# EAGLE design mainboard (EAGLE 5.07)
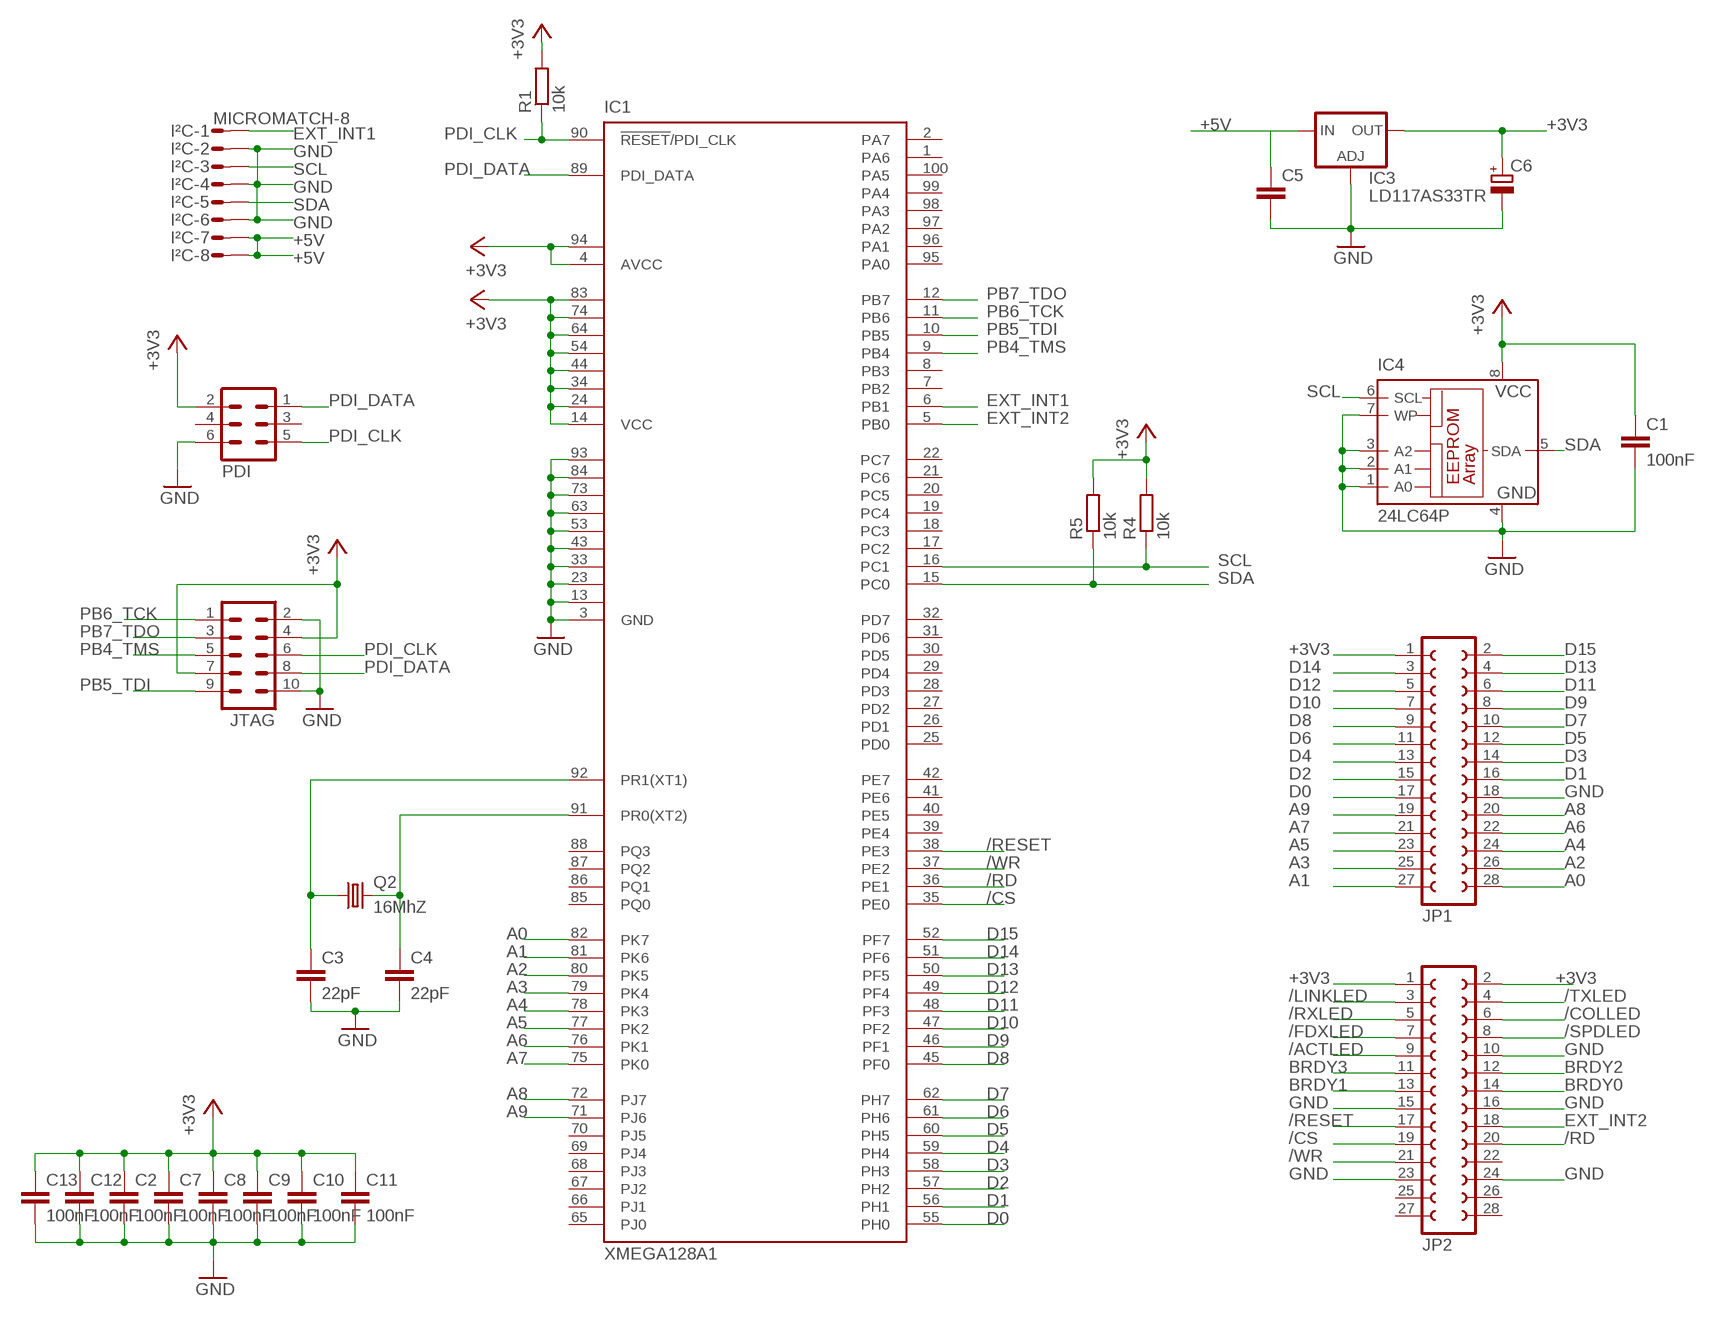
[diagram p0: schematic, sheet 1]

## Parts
C1  100nF  C-EUC0805  [C0805]
C2  100nF  C-EUC0805  [C0805]
C3  22pF  C-EUC0805  [C0805]
C4  22pF  C-EUC0805  [C0805]
C5  C-EUC0805  [C0805]
C6  CPOL-EU085CS-1AR  [085CS_1AR]
C7  100nF  C-EUC0805  [C0805]
C8  100nF  C-EUC0805  [C0805]
C9  100nF  C-EUC0805  [C0805]
C10  100nF  C-EUC0805  [C0805]
C11  100nF  C-EUC0805  [C0805]
C12  100nF  C-EUC0805  [C0805]
C13  100nF  C-EUC0805  [C0805]
IC1  XMEGA128A1  [TQFP100]
IC3  LD117AS33TR  [SOT223]
IC4  24LC64P  [DIL8]
I²C  MICROMATCH-8  [MICROMATCH-8]
JP1  FE15-2  [FE15-2]
JP2  FE15-2  [FE15-2]
JTAG  MA05-2  [MA05-2]
PDI  MA03-2  [MA03-2]
Q2  16MhZ  CRYSTALSM49  [SM49]
R1  10k  R-EU_M0805  [M0805]
R4  10k  R-EU_M0805  [M0805]
R5  10k  R-EU_M0805  [M0805]

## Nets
+3V3: C1.1 C2.1 C6.+ C7.1 C8.1 C9.1 C10.1 C11.1 C12.1 C13.1 IC1.4(AVCC) IC1.14(VCC) IC1.24(VCC1) IC1.34(VCC2) IC1.44(VCC3) IC1.54(VCC4) IC1.64(VCC5) IC1.74(VCC6) IC1.83(VCC7) IC1.94(AVCC1) IC3.4(OUT) IC4.8(VCC) JP1.1 JP2.1 JP2.2 JTAG.4 JTAG.7 PDI.2 R1.2 R4.2 R5.2
+5V: C5.1 IC3.3(IN) I²C.7 I²C.8
/ACTLED: JP2.9
/COLLED: JP2.6
/CS: IC1.35(PE0) JP2.19
/FDXLED: JP2.7
/LINKLED: JP2.3
/RD: IC1.36(PE1) JP2.20
/RESET: IC1.38(PE3) JP2.17
/RXLED: JP2.5
/SPDLED: JP2.8
/TXLED: JP2.4
/WR: IC1.37(PE2) JP2.21
A0: IC1.82(PK7) JP1.28
A1: IC1.81(PK6) JP1.27
A2: IC1.80(PK5) JP1.26
A3: IC1.79(PK4) JP1.25
A4: IC1.78(PK3) JP1.24
A5: IC1.77(PK2) JP1.23
A6: IC1.76(PK1) JP1.22
A7: IC1.75(PK0) JP1.21
A8: IC1.72(PJ7) JP1.20
A9: IC1.71(PJ6) JP1.19
BRDY0: JP2.14
BRDY1: JP2.13
BRDY2: JP2.12
BRDY3: JP2.11
D0: IC1.55(PH0) JP1.17
D1: IC1.56(PH1) JP1.16
D2: IC1.57(PH2) JP1.15
D3: IC1.58(PH3) JP1.14
D4: IC1.59(PH4) JP1.13
D5: IC1.60(PH5) JP1.12
D6: IC1.61(PH6) JP1.11
D7: IC1.62(PH7) JP1.10
D8: IC1.45(PF0) JP1.9
D9: IC1.46(PF1) JP1.8
D10: IC1.47(PF2) JP1.7
D11: IC1.48(PF3) JP1.6
D12: IC1.49(PF4) JP1.5
D13: IC1.50(PF5) JP1.4
D14: IC1.51(PF6) JP1.3
D15: IC1.52(PF7) JP1.2
EXT_INT1: IC1.6(PB1) I²C.1
EXT_INT2: IC1.5(PB0) JP2.18
GND: C1.2 C2.2 C3.2 C4.2 C5.2 C6.- C7.2 C8.2 C9.2 C10.2 C11.2 C12.2 C13.2 IC1.3(GND) IC1.13(GND1) IC1.23(GND2) IC1.33(GND3) IC1.43(GND4) IC1.53(GND5) IC1.63(GND6) IC1.73(GND7) IC1.84(GND8) IC1.93(GND9) IC3.1(ADJ) IC4.1(A0) IC4.2(A1) IC4.3(A2) IC4.4(GND) IC4.7(WP) I²C.2 I²C.4 I²C.6 JP1.18 JP2.10 JP2.15 JP2.16 JP2.23 JP2.24 JTAG.2 JTAG.10 PDI.6
N$5: C3.1 IC1.92(PR1(XT1)) Q2.1
N$6: C4.1 IC1.91(PR0(XT2)) Q2.2
PB4_TMS: IC1.9(PB4) JTAG.5
PB5_TDI: IC1.10(PB5) JTAG.9
PB6_TCK: IC1.11(PB6) JTAG.1
PB7_TDO: IC1.12(PB7) JTAG.3
PDI_CLK: IC1.90(!RESET!/PDI_CLK) JTAG.6 PDI.5 R1.1
PDI_DATA: IC1.89(PDI_DATA) JTAG.8 PDI.1
SCL: IC1.16(PC1) IC4.6(SCL) I²C.3 R4.1
SDA: IC1.15(PC0) IC4.5(SDA) I²C.5 R5.1
Unconnected: IC1.1(PA6) IC1.2(PA7) IC1.7(PB2) IC1.8(PB3) IC1.17(PC2) IC1.18(PC3) IC1.19(PC4) IC1.20(PC5) IC1.21(PC6) IC1.22(PC7) IC1.25(PD0) IC1.26(PD1) IC1.27(PD2) IC1.28(PD3) IC1.29(PD4) IC1.30(PD5) IC1.31(PD6) IC1.32(PD7) IC1.39(PE4) IC1.40(PE5) IC1.41(PE6) IC1.42(PE7) IC1.65(PJ0) IC1.66(PJ1) IC1.67(PJ2) IC1.68(PJ3) IC1.69(PJ4) IC1.70(PJ5) IC1.85(PQ0) IC1.86(PQ1) IC1.87(PQ2) IC1.88(PQ3) IC1.95(PA0) IC1.96(PA1) IC1.97(PA2) IC1.98(PA3) IC1.99(PA4) IC1.100(PA5) JP2.22 JP2.25 JP2.26 JP2.27 JP2.28 PDI.3 PDI.4

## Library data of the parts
C1-C5 C7-C13 = rcl:C-EU: CAPACITOR, European symbol
C6 = rcl:CPOL-EU: POLARIZED CAPACITOR, European symbol
IC1 = atmel:XMEGA128A1: MICROCONTROLLER Features High-performance, Low-power 8/16-bit AVR XMEGA Microcontroller Non-Volatile Program and Data Memories - 64K - 384K Bytes of In-System Self-Programmable Flash - 4K - 8K Bytes Boot Section with Independent Lock Bits - 2 KB - 4 KB EEPROM - 4 KB - 32 KB Internal SRAM External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
IC3 = v-reg:LD117A?*: Low drop fixed and adjustable positive voltage regulators 1 A Source: http://www.st.com/stonline/products/literature/ds/7194/ld1117axx.pdf
IC4 = microchip:24*: Serial EEPROM I2C
I²C = con-amp-micromatch:MICROMATCH-8: MicroMaTch 8 7-215464-8 / 0-215464-8 Drawing Number C-215464 DDEController.pdf
JP1 JP2 = con-FE-neu:FE15-2: FEMALE HEADER
JTAG = con-lstb:MA05-2: PIN HEADER
PDI = con-lstb:MA03-2: PIN HEADER
Q2 = crystal:CRYSTAL: CRYSTAL
R1 R4 R5 = rcl:R-EU_: RESISTOR, European symbol

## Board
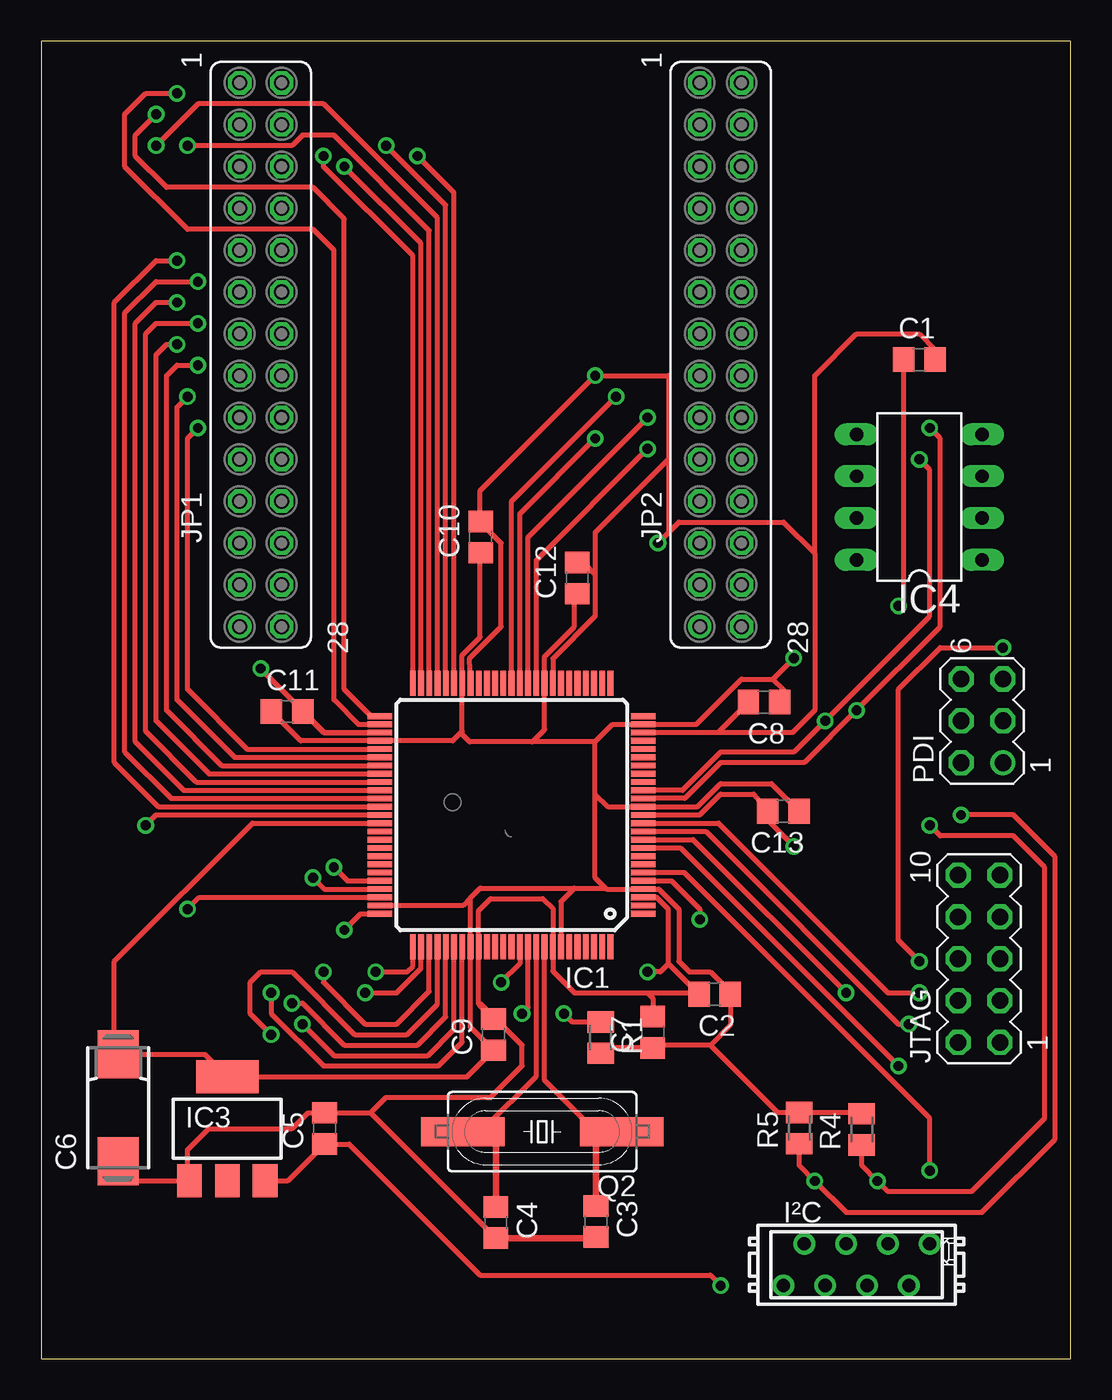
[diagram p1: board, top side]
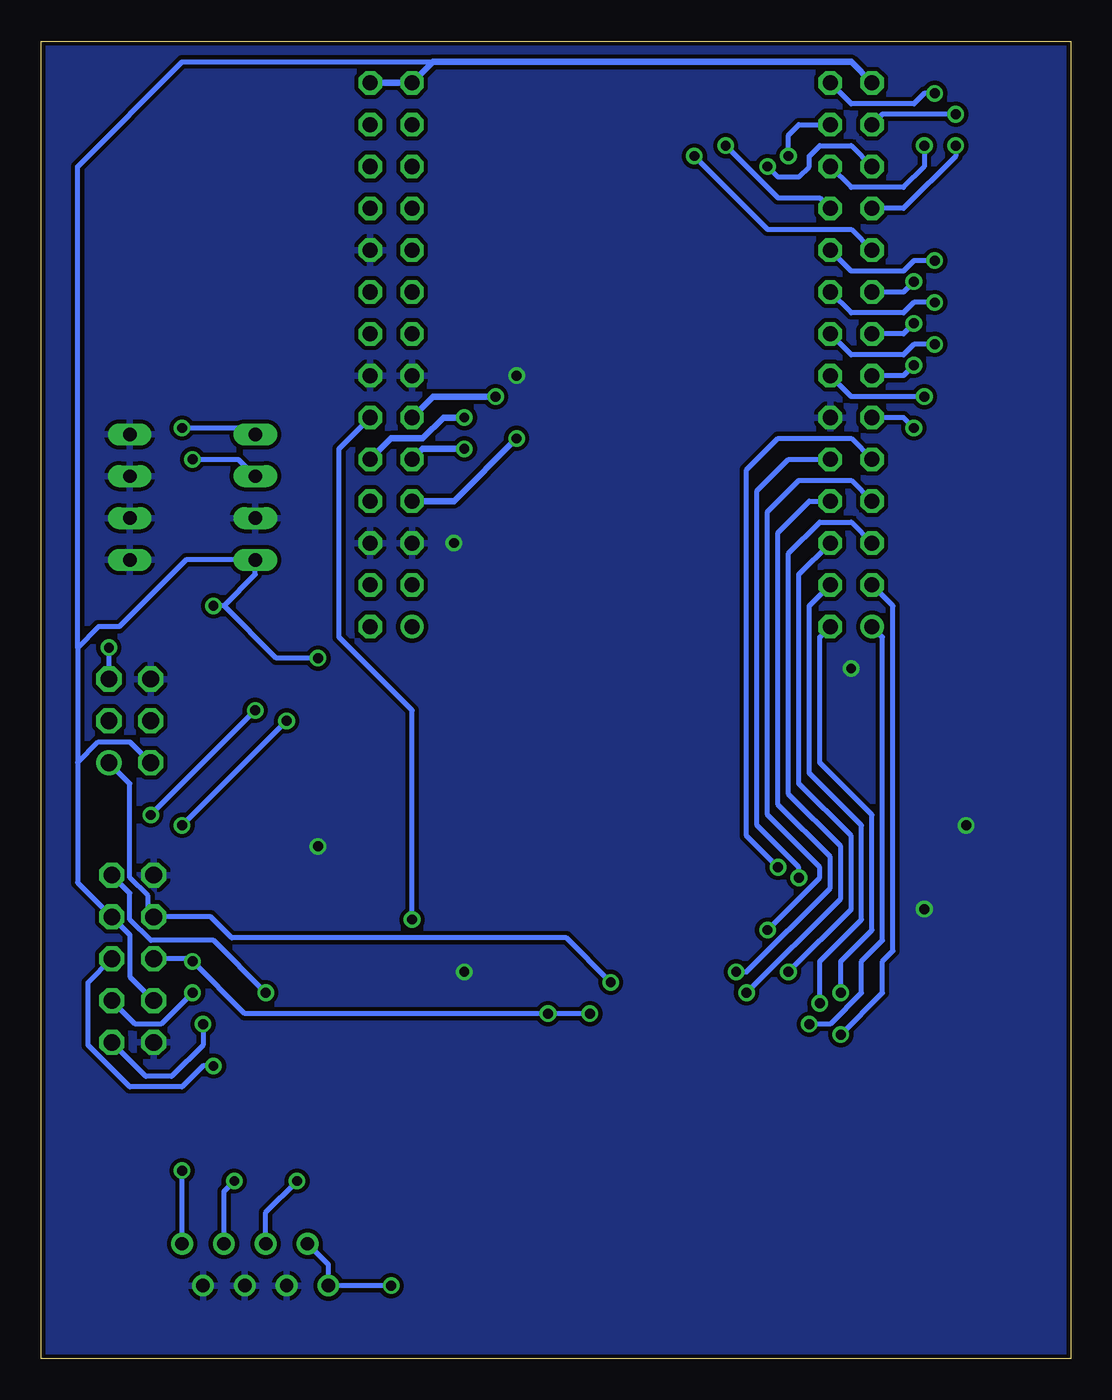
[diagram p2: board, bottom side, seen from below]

Size 62.54 x 80 mm. Coordinates in mm from the lower left corner, seen from the top.
Outline: 0,0 62.54,0 62.54,80 0,80 0,0
Copper layers (1*16): Top 0.035mm / dielectric 1.5mm / Bottom 0.035mm
Design rules "EMST": minimum track width 10mil, minimum drill 0.6mm, track to track 10mil, track to pad 10mil, pad to pad 10mil, via to via 10mil, smd to smd 8mil, copper to edge 10mil, drill to drill 10mil, minimum pad ring 10mil, minimum via ring 8mil, stop-mask expansion 4mil, vias tented up to drill 0mil, thermal gap 10mil

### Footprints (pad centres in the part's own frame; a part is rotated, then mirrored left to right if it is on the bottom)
C0805 = smd 1.3 x 1.5: 1 -0.95,0; 2 0.95,0
085CS_1AR = smd 2.9 x 2.5: + 3.25,0; - -3.25,0
TQFP100 = smd 1.5 x 0.35: 1 -8,6; 2 -8,5.5; 3 -8,5; 4 -8,4.5; 5 -8,4; 6 -8,3.5; 7 -8,3; 8 -8,2.5; 9 -8,2; 10 -8,1.5; 11 -8,1; 12 -8,0.5; 13 -8,0; 14 -8,-0.5; 15 -8,-1; 16 -8,-1.5; 17 -8,-2; 18 -8,-2.5; 19 -8,-3; 20 -8,-3.5; 21 -8,-4; 22 -8,-4.5; 23 -8,-5; 24 -8,-5.5; 25 -8,-6; 51 8,-6; 52 8,-5.5; 53 8,-5; 54 8,-4.5; 55 8,-4; 56 8,-3.5; 57 8,-3; 58 8,-2.5; 59 8,-2; 60 8,-1.5; 61 8,-1; 62 8,-0.5; 63 8,0; 64 8,0.5; 65 8,1; 66 8,1.5; 67 8,2; 68 8,2.5; 69 8,3; 70 8,3.5; 71 8,4; 72 8,4.5; 73 8,5; 74 8,5.5; 75 8,6 | smd 0.35 x 1.5: 26 -6,-8; 27 -5.5,-8; 28 -5,-8; 29 -4.5,-8; 30 -4,-8; 31 -3.5,-8; 32 -3,-8; 33 -2.5,-8; 34 -2,-8; 35 -1.5,-8; 36 -1,-8; 37 -0.5,-8; 38 0,-8; 39 0.5,-8; 40 1,-8; 41 1.5,-8; 42 2,-8; 43 2.5,-8; 44 3,-8; 45 3.5,-8; 46 4,-8; 47 4.5,-8; 48 5,-8; 49 5.5,-8; 50 6,-8; 76 6,8; 77 5.5,8; 78 5,8; 79 4.5,8; 80 4,8; 81 3.5,8; 82 3,8; 83 2.5,8; 84 2,8; 85 1.5,8; 86 1,8; 87 0.5,8; 88 0,8; 89 -0.5,8; 90 -1,8; 91 -1.5,8; 92 -2,8; 93 -2.5,8; 94 -3,8; 95 -3.5,8; 96 -4,8; 97 -4.5,8; 98 -5,8; 99 -5.5,8; 100 -6,8
SOT223 = smd 1.5 x 2: 1 -2.3,-3.15; 2 0,-3.15; 3 2.3,-3.15 | smd 3.8 x 2: 4 0,3.15
DIL8 = drill 0.813 long: 1 -3.81,-3.81; 2 -1.27,-3.81; 3 1.27,-3.81; 4 3.81,-3.81; 5 3.81,3.81; 6 1.27,3.81; 7 -1.27,3.81; 8 -3.81,3.81
MICROMATCH-8 = drill 0.813 round: 1 4.445,1.27; 2 3.175,-1.27; 3 1.905,1.27; 4 0.635,-1.27; 5 -0.635,1.27; 6 -1.905,-1.27; 7 -3.175,1.27; 8 -4.445,-1.27
FE15-2 = drill 0.914 octagon: 1 15.24,1.27; 2 15.24,-1.27; 3 12.7,1.27; 4 12.7,-1.27; 5 10.16,1.27; 6 10.16,-1.27; 7 7.62,1.27; 8 7.62,-1.27; 9 5.08,1.27; 10 5.08,-1.27; 11 2.54,1.27; 12 2.54,-1.27; 13 0,1.27; 14 0,-1.27; 15 -2.54,1.27; 16 -2.54,-1.27; 17 -5.08,1.27; 18 -5.08,-1.27; 19 -7.62,1.27; 20 -7.62,-1.27; 21 -10.16,1.27; 22 -10.16,-1.27; 23 -12.7,1.27; 24 -12.7,-1.27; 25 -15.24,1.27; 26 -15.24,-1.27; 28 -17.78,-1.27 | drill 0.914 round: 27 -17.78,1.27
MA05-2 = drill 1.016 octagon: 1 -5.08,-1.27; 2 -5.08,1.27; 3 -2.54,-1.27; 4 -2.54,1.27; 5 0,-1.27; 6 0,1.27; 7 2.54,-1.27; 8 2.54,1.27; 9 5.08,-1.27; 10 5.08,1.27
MA03-2 = drill 1.016 round: 1 -2.54,-1.27 | drill 1.016 octagon: 2 -2.54,1.27; 3 0,-1.27; 4 0,1.27; 5 2.54,-1.27; 6 2.54,1.27
SM49 = smd 5.08 x 1.778: 1 -4.826,0; 2 4.826,0
M0805 = smd 1.3 x 1.6: 1 -0.95,0; 2 0.95,0

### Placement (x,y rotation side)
C1  53.34,60.66 0 top
C2  40.91,22.13 180 top
C3  33.7,8.34 270 top
C4  27.62,8.28 270 top
C5  17.22,13.99 90 top
C6  4.68,15.24 90 top
C7  37.16,19.83 90 top
C8  43.91,39.87 180 top
C9  27.48,19.68 90 top
C10  26.7,49.89 90 top
C11  14.94,39.3 0 top
C12  32.56,47.4 90 top
C13  45.09,33.25 180 top
IC1  28.58,33.02 180 top
IC3  11.3,13.97 0 top
IC4  53.34,52.31 90 top
I²C  49.53,5.71 0 top
JP1  13.33,62.23 90 top
JP2  41.27,62.23 90 top
JTAG  56.97,24.29 90 top
PDI  57.15,38.73 90 top
Q2  30.44,13.79 180 top
R1  33.98,19.5 270 top
R4  49.84,13.93 90 top
R5  46.05,14.01 90 top

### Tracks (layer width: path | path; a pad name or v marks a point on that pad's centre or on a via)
+3V3  (via drill 0.6)
  Top 0.305: C11.1 15.77,37.52 IC1.54 25,37.52 25.58,38.1 | C13.1 44.36,34.92 41.27,34.92 39.87,33.52 IC1.14 34.43,33.52 33.66,34.29 | C10.1 26.67,48.91 26.67,43.81 25.58,42.72 IC1.44 25.58,38.1 | C12.1 32.38,46.27 32.38,44.45 30.58,42.64 IC1.34 30.58,38.2 29.85,37.47 | 33.66,37.47 34.71,38.52 IC1.24 39.79,38.52 42.55,41.27 44.45,41.27 | C8.1 45.09,40.09 45.09,40.64 44.45,41.27 | 33.66,34.29 33.66,37.47 | 34.29,28.57 33.66,29.21 33.66,34.29 | 34.29,28.57 34.34,28.52 IC1.4 37.52,28.52 38.73,27.3 38.73,24.13 39.37,23.5 40.64,23.5 41.86,22.27 C2.1 41.86,20.27 40.64,19.05 | IC1.94 31.58,27.77 32.38,28.57 | 32.38,28.57 34.29,28.57 | 26.08,27.98 IC1.83 26.08,20.14 C9.1 25.87,17.12 IC3.4 9.93,18.49 C6.+ 4.45,18.73 4.45,24.13 12.83,32.52 IC1.64 | 26.08,27.98 26.67,28.57 32.38,28.57 | 33.66,37.47 29.85,37.47 | R4.2 49.76,14.96 R5.2 44.73,14.96 40.64,19.05 | 26.08,27.98 25.62,27.52 IC1.74 | v52.07,45.72 52.39,46.03 52.38,46.03 v52.07,45.72 | C1.1 52.39,46.04 v52.07,45.72 | 29.85,37.47 26.04,37.47 25.58,37.92 25.58,38.1 | 44.45,41.27 v45.72,42.55 | 40.64,19.05 37.33,19.05 C7.1 34.3,18.88 R1.2
  Top 0.406: C12.1 32.41,46.29
  Bottom 0.305: JTAG.4 57.15,23.2 57.15,25.74 JTAG.7 60.33,28.91 60.33,36.2 | 60.33,36.2 59.05,37.47 57.15,37.47 PDI.2 | 60.33,43.18 59.05,44.45 57.79,44.45 53.73,48.51 IC4.8 49.53,47.62 51.44,45.72 | 60.33,43.18 60.33,36.2 | 38.73,78.74 53.98,78.74 60.33,72.39 60.33,43.18 | 51.44,45.72 v52.07,45.72 | v45.72,42.55 48.26,42.55 51.44,45.72
  Bottom 0.406: JP1.1 13.33,78.74 38.73,78.74 JP2.1 JP2.2
+5V  (via drill 0.6)
  Top 0.305: IC3.3 15,10.82 C5.1 18.71,13.04 26.67,5.08 40.64,5.08 v41.27,4.45
  Bottom 0.305: v41.27,4.45 I²C.8 45.09,5.71 I²C.7
/CS  (via drill 0.6)
  Top 0.305: IC1.35 30.08,48.49 v36.83,55.24
  Bottom 0.406: v36.83,55.24 39.37,55.24 JP2.19
/RD  (via drill 0.6)
  Top 0.305: IC1.36 29.58,49.9 v36.83,57.15
  Bottom 0.406: v36.83,57.15 38.1,57.15 39.37,55.88 41.27,55.88 JP2.20
/RESET  (via drill 0.6)
  Top 0.305: IC1.38 28.58,52.07 v34.93,58.42
  Bottom 0.406: v34.93,58.42 38.73,58.42 JP2.17
/WR  (via drill 0.6)
  Top 0.305: IC1.37 29.08,51.3 v33.66,55.88
  Bottom 0.406: v33.66,55.88 37.47,52.07 JP2.21
A0  (via drill 0.6 pad 0.3)
  Top 0.305: IC1.82 25.58,19.23 24.13,17.78 17.14,17.78 13.97,20.95 v13.97,22.23
  Bottom 0.305: v13.97,22.23 13.97,24.13 12.06,26.04 12.06,33.02 15.24,36.2 15.24,43.81 JP1.28
A1  (via drill 0.6 pad 0.3)
  Top 0.305: IC1.81 25.08,20 23.5,18.41 17.78,18.41 v15.88,20.32
  Bottom 0.305: JP1.27 11.43,43.81 11.43,25.4 12.7,24.13 12.7,22.23 14.6,20.32 v15.88,20.32
A2  (via drill 0.6 pad 0.3)
  Top 0.305: IC1.80 24.58,20.77 22.86,19.05 18.42,19.05 15.88,21.59 v15.24,21.59
  Bottom 0.305: v15.24,21.59 15.24,24.13 12.7,26.67 12.7,32.38 15.88,35.56 15.88,45.72 JP1.26
A3  (via drill 0.6 pad 0.3)
  Top 0.305: IC1.79 24.08,21.54 22.23,19.68 19.05,19.68 15.24,23.5 13.33,23.5 12.7,22.86 12.7,20.95 v13.97,19.68
  Bottom 0.305: v13.97,19.68 11.43,22.23 11.43,24.13 10.79,24.77 10.79,45.72 JP1.25
A4  (via drill 0.6 pad 0.3)
  Top 0.305: IC1.78 23.58,22.3 21.59,20.32 19.69,20.32 17.14,22.86 v17.14,23.5
  Bottom 0.305: v17.14,23.5 13.33,27.3 13.33,31.75 16.51,34.92 16.51,47.62 JP1.24
A5  (via drill 0.6 pad 0.3)
  Top 0.305: IC1.77 23.08,23.71 21.59,22.23 v19.69,22.23
  Bottom 0.305: v19.69,22.23 13.97,27.94 13.97,31.11 17.14,34.29 17.14,48.9 15.24,50.8 13.33,50.8 JP1.23
A6  (via drill 0.6 pad 0.3)
  Top 0.305: IC1.76 22.58,23.84 22.23,23.5 v20.32,23.5
  Bottom 0.305: v20.32,23.5 19.69,23.5 14.6,28.57 14.6,30.48 17.78,33.66 17.78,50.16 15.88,52.07 JP1.22
A7  (via drill 0.6 pad 0.3)
  Top 0.305: IC1.75 19.4,27.02 v18.42,26.04
  Bottom 0.305: JP1.21 13.33,53.34 16.51,53.34 18.42,51.44 18.42,33.02 15.24,29.84 15.24,29.21 v18.42,26.04
A8  (via drill 0.6 pad 0.3)
  Top 0.305: IC1.72 17.2,28.52 v16.51,29.21
  Bottom 0.305: JP1.20 17.14,54.61 19.05,52.7 19.05,32.38 16.51,29.84 v16.51,29.21
A9  (via drill 0.6 pad 0.3)
  Top 0.305: IC1.71 18.61,29.02 v17.78,29.84
  Bottom 0.305: JP1.19 13.33,55.88 17.78,55.88 19.69,53.98 19.69,31.75 v17.78,29.84
D0  (via drill 0.6)
  Top 0.305: v9.53,56.52 8.89,55.88 8.89,40.64 12.51,37.02 IC1.55
  Bottom 0.305: v9.53,56.52 10.16,57.15 JP1.17
D1  (via drill 0.6)
  Top 0.305: v8.89,58.42 8.25,57.78 8.25,40.01 11.74,36.52 IC1.56
  Bottom 0.305: v8.89,58.42 13.33,58.42 JP1.16
D2  (via drill 0.6)
  Top 0.305: IC1.57 10.97,36.02 7.62,39.37 7.62,59.69 8.25,60.33 v9.53,60.33
  Bottom 0.305: v9.53,60.33 10.16,59.69 JP1.15
D3  (via drill 0.6)
  Top 0.305: IC1.58 10.2,35.52 6.99,38.73 6.99,60.96 7.62,61.59 v8.25,61.59
  Bottom 0.305: JP1.14 13.33,60.96 10.16,60.96 9.53,61.59 v8.25,61.59
D4  (via drill 0.6)
  Top 0.305: IC1.59 9.43,35.02 6.35,38.1 6.35,62.23 6.99,62.87 v9.53,62.87
  Bottom 0.305: v9.53,62.87 10.16,62.23 JP1.13
D5  (via drill 0.6)
  Top 0.305: IC1.60 8.66,34.52 5.71,37.47 5.71,62.87 6.99,64.14 v8.25,64.14
  Bottom 0.305: JP1.12 13.33,63.5 10.16,63.5 9.53,64.14 v8.25,64.14
D6  (via drill 0.6)
  Top 0.305: IC1.61 7.89,34.02 5.08,36.83 5.08,63.5 6.99,65.41 v9.53,65.41
  Bottom 0.305: v9.53,65.41 10.16,64.77 JP1.11
D7  (via drill 0.6)
  Top 0.305: IC1.62 7.12,33.52 4.45,36.2 4.45,64.14 6.99,66.67 v8.25,66.67
  Bottom 0.305: JP1.10 13.33,66.04 10.16,66.04 9.53,66.67 v8.25,66.67
D8  (via drill 0.6)
  Top 0.305: IC1.45 25.08,70.81 v22.86,73.03
  Bottom 0.305: JP1.9 13.33,68.58 18.42,68.58 v22.86,73.03
D9  (via drill 0.6)
  Top 0.305: IC1.46 24.58,70.04 v20.96,73.66
  Bottom 0.305: v20.96,73.66 17.78,70.48 15.24,70.48 JP1.8
D10  (via drill 0.6)
  Top 0.305: IC1.47 24.08,69.27 17.14,76.2 9.53,76.2 v6.99,73.66
  Bottom 0.305: v6.99,73.66 6.99,73.03 10.16,69.85 JP1.7
D11  (via drill 0.6)
  Top 0.305: IC1.48 23.58,68.5 17.78,74.3 15.88,74.3 15.24,73.66 v8.89,73.66
  Bottom 0.305: v8.89,73.66 8.89,72.39 10.16,71.12 13.33,71.12 JP1.6
D12  (via drill 0.6)
  Top 0.305: IC1.49 23.08,67.73 v18.42,72.39
  Bottom 0.305: v18.42,72.39 17.78,71.75 16.51,71.75 15.88,72.39 15.88,73.03 15.24,73.66 13.33,73.66 JP1.5
D13  (via drill 0.6)
  Top 0.305: IC1.50 22.58,66.96 17.14,72.39 v17.14,73.03
  Bottom 0.305: v17.14,73.03 17.14,74.3 16.51,74.93 JP1.4
D14  (via drill 0.6)
  Top 0.305: IC1.51 20.04,39.02 20.04,39.09 19.97,39.09 18.42,40.64 18.42,69.22 16.51,71.12 7.62,71.12 5.71,73.03 5.71,74.3 v6.99,75.56
  Bottom 0.305: v6.99,75.56 11.43,75.56 JP1.3
D15  (via drill 0.6)
  Top 0.305: IC1.52 19.27,38.52 17.78,40.01 17.78,67.31 16.51,68.58 8.89,68.58 5.08,72.39 5.08,75.56 6.35,76.83 v8.25,76.83
  Bottom 0.305: v8.25,76.83 8.89,76.83 9.53,76.2 13.33,76.2 JP1.2
EXT_INT1  (via drill 0.6)
  Top 0.305: IC1.6 39.06,29.52 53.98,14.61 v53.98,11.43
  Bottom 0.305: I²C.1 v53.98,11.43
EXT_INT2  (via drill 0.6 pad 0.3)
  Top 0.305: IC1.5 38.29,29.02 40.01,27.3 v40.01,26.67
  Bottom 0.305: v40.01,26.67 40.01,39.37 44.45,43.81 44.45,55.24 JP2.18
GND  (via drill 0.6)
  Top 0.305: 33.66,47.62 33.66,45.09 31.08,42.51 IC1.33 | 33.66,47.62 33.02,48.26 32.66,48.26 C12.2 | IC1.43 26.04,42.55 27.94,44.45 27.94,49.53 26.7,50.77 C10.2 26.67,50.87 26.67,52.7 v33.66,59.69 38.1,59.69 38.1,54.61 | C11.2 17.17,38.02 IC1.53 17.23,38.02 v13.33,41.91 | IC1.13 40.01,33.02 41.27,34.29 43.27,34.29 C13.2 44.13,32.7 v45.72,31.11 | 26.58,21.54 IC1.84 26.58,27.21 27.3,27.94 30.48,27.94 31.08,27.34 IC1.93 31.08,23.54 32.38,22.23 36.83,22.23 | 26.58,21.54 C9.2 | 33.66,47.62 33.66,50.16 38.1,54.61 | 38.1,54.61 38.1,50.16 v37.47,49.53 38.73,50.8 45.09,50.8 46.99,48.9 | 41.11,38.02 IC1.23 | 41.11,38.02 C8.2 | 41.11,38.02 45.64,38.02 46.99,39.37 46.99,48.9 | 20.01,14.94 C5.2 16.21,14.94 15.24,13.97 10.16,13.97 8.89,12.7 8.89,10.94 IC3.1 5.86,10.82 C6.- | 20.01,14.94 C4.2 | IC1.3 37.38,28.02 38.1,27.3 38.1,23.99 | 38.1,23.99 C2.2 39.87,22.23 36.83,22.23 | v36.83,23.5 37.61,23.5 38.1,23.99 | IC1.63 6.99,33.02 v6.35,32.38 | IC1.73 9.61,28.02 v8.89,27.3 | 26.58,21.54 26.72,21.54 29.21,19.05 29.21,17.78 27.3,15.88 20.94,15.88 20.01,14.94 | C1.2 54.29,61.28 53.34,62.23 49.53,62.23 46.99,59.69 46.99,48.9 | C7.2 37.16,21.9 36.83,22.23
  Top 0.406: C4.2 33.63,7.33 C3.2
  pour Bottom: 0,80.01 62.87,80.01 62.87,0 0,0
N$5
  Top 0.305: IC1.92 30.58,16.91 33.7,13.79
  Top 0.406: Q2.1 34.97,13.5 34.41,13.5 34.16,13.75 33.7,13.79 C3.1
N$6
  Top 0.305: IC1.91 30.08,17.17 26.91,14
  Top 0.406: Q2.2 25.9,13.5 26.41,13.5 26.91,14 27.62,13.29 C4.1
PB4_TMS  (via drill 0.6 pad 0.3)
  Top 0.305: IC1.9 38.83,31.02 v52.07,17.78
  Bottom 0.305: v52.07,17.78 52.7,17.78 53.98,16.51 57.15,16.51 59.69,19.05 59.69,22.84 JTAG.5
PB5_TDI  (via drill 0.6 pad 0.3)
  Top 0.305: IC1.10 39.6,31.52 v48.9,22.23
  Bottom 0.305: JTAG.9 57.15,28.28 57.15,26.67 55.88,25.4 52.07,25.4 v48.9,22.23
PB6_TCK  (via drill 0.6 pad 0.3)
  Top 0.305: IC1.11 40.37,32.02 52.07,20.32 v52.7,20.32
  Bottom 0.305: v52.7,20.32 52.7,19.05 54.61,17.14 56.18,17.14 JTAG.1
PB7_TDO  (via drill 0.6 pad 0.3)
  Top 0.305: IC1.12 41.14,32.52 51.44,22.23 v53.34,22.23
  Bottom 0.305: v53.34,22.23 55.25,20.32 56.81,20.32 JTAG.3
PDI_CLK  (via drill 0.6)
  Top 0.305: v58.42,43.18 54.61,43.18 52.07,40.64 52.07,25.4 v53.34,24.13 | IC1.90 29.58,21.32 v29.21,20.95 | R1.1 32.25,20.45 v31.75,20.95
  Bottom 0.305: JTAG.6 53.5,24.29 v53.34,24.13 50.16,20.95 v31.75,20.95 v29.21,20.95 | v58.42,43.18 PDI.5
PDI_DATA  (via drill 0.6)
  Top 0.305: IC1.89 29.08,24 v27.94,22.86
  Bottom 0.305: PDI.1 57.15,34.92 57.15,29.21 56.04,28.1 56.04,26.83 JTAG.8 52.23,26.83 50.96,25.56 30.64,25.56 v27.94,22.86
SCL  (via drill 0.6)
  Top 0.305: IC1.16 38.97,34.52 41.27,36.83 45.72,36.83 v47.62,38.73 53.98,45.09 53.98,53.98 v53.34,54.61 | R4.1 49.84,11.76 v50.8,10.79 51.44,10.16 56.52,10.16 60.96,14.61 60.96,29.84 59.05,31.75 54.61,31.75 v53.98,32.38
  Bottom 0.305: v53.34,54.61 50.55,54.61 IC4.6 | I²C.3 51.44,10.16 v50.8,10.79 | v53.98,32.38 v47.62,38.73
SDA  (via drill 0.6)
  Top 0.305: IC1.15 39.1,34.02 41.27,36.2 46.36,36.2 v49.53,39.37 54.61,44.45 54.61,55.88 v53.98,56.52 | R5.1 46.05,11.74 v46.99,10.79 48.9,8.89 57.15,8.89 61.59,13.34 61.59,30.48 59.05,33.02 v55.88,33.02
  Bottom 0.305: v53.98,56.52 49.92,56.52 IC4.5 | I²C.5 48.9,8.89 v46.99,10.79 | v55.88,33.02 v49.53,39.37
